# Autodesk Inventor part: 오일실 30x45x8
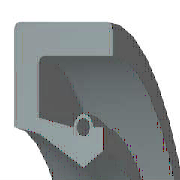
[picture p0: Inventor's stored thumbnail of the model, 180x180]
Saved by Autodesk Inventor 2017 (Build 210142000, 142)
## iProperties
IsCustomPart: 1
Created: 2012-02
Part Number: 오일실 30x45x8
Material: 고무
Document SubType Name: Modeling
Standard: JIS B 2402
Designer: mdu-01
Standards Organization: JIS
Language: ko-KR
Size Designation: 30 45 8 A
Categories: <MemberInstance><Categories><Category DisplayName="샤프트 부품" InternalName="7f7aeb1f-a693-4053-b835-cee3144e0d98" Mnemonic="SHFT"><Category DisplayName="실링" Intern
Density: 0.93 g/cm^3
Appearance: Rubber-Black
Author: mdu-01
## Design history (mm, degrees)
body "Solid1"
revolve "회전1" stored, may be unused: angle "d33" = 360 deg
fillet "모깎기1" dims "d34" = 0.4 (= 0.05 x b)
sketch "스케치2"
  geometry: L1 (16.821, -5.895)-(17.526, -8); L2 (16.071, -5.2)-(16.821, -5.895); L3 (15, -2)-(16.071, -5.2); L4 (16, -1)-(15, -2); L5 (17.676, -1)-(16, -1); L6 (17.676, -1.8)-(17.676, -1); L7 (17.676, -6)-(17.676, -3.4); L8 (19.5, -6)-(17.676, -6); L9 (21, -2)-(19.5, -6); L10 (21, 0)-(21, -2); L11 (22.5, 0)-(21, 0); L12 (22.5, -8)-(22.5, 0); L13 (17.526, -8)-(22.5, -8); L14 (0, -9.6)-(0, 1.6) reference; L15 (28, 0)-(14, 0) reference; A1 r 0.8 centre (17.676, -2.6) between (17.676, -3.4) and (17.676, -1.8)
  constraints: 26 end point, 4 horizontal, 4 vertical, 2 point on circle, 1 centre point, 1 collinear, 1 parallel
  dimensions: "d2" = 8 distance of L12.start L11.start (= b); "d4" = 1 vertical distance of L10.start L5.start (= 0.125 x b); "d6" = 1.5 distance of L11.start L10.start (= 0.1 x dd - 0.1 x Diam); "d8" = 2 distance of L10.start L9.start (= 0.25 x b); "d10" = 2 vertical distance of L8.start L1.end (= 0.25 x b); "d12" = 1.5 horizontal distance of L9.start L8.start (= 0.1 x dd - 0.1 x Diam); "d14" = 0.8 radius of A1 (= 0.1 x b); "d16" = 0 horizontal distance of A1.centre L7.end; "d18" = 0.8 distance of L6.start L5.start (= 0.1 x b); "d20" = 1 horizontal distance of L4.start L3.start (= 0.0666667 x dd - 0.0666667 x Diam); "d22" = 0.15 horizontal distance of L7.start L1.end (= 0.01 x dd - 0.01 x Diam); "d24" = 1 horizontal distance of L4.start L3.start (= 0.125 x b); "d26" = 3.2 vertical distance of L3.start L2.start (= 0.4 x b); "d28" = 1.07143 horizontal distance of L3.start L2.start (= 0.0714286 x dd - 0.0714286 x Diam); "d30" = 2.10526 vertical distance of L1.start L1.end (= 0.263158 x b); "d32" = 0.75 horizontal distance of L2.start L1.start (= 0.05 x dd - 0.05 x Diam); "d37" = 0 distance between parallel lines of L15 L11; "d38" = 22.5 distance between parallel lines of L14 L12 (= 0.5 x dd); "d39" = 15 distance from line of L14 L3.start (= 0.5 x Diam)
other parameters: "dd" = 45 [user parameter; used in 7 equation terms], "b" = 8 [user parameter; used in 10 equation terms], "d1" = 8 (derived), "d3" = 1 (derived), "d5" = 2 (derived), "d7" = 2 (derived), "d9" = 2 (derived), "d11" = 2 (derived), "d13" = 0.8 (derived), "d15" = 0 (derived), "d17" = 0.8 (derived), "d19" = 1.33333 (derived), "d21" = 0.2 (derived), "d23" = 1 (derived), "d25" = 3.2 (derived), "d27" = 1.42857 (derived), "d29" = 2.10526 (derived), "d31" = 1 (derived), "d40" = 0
